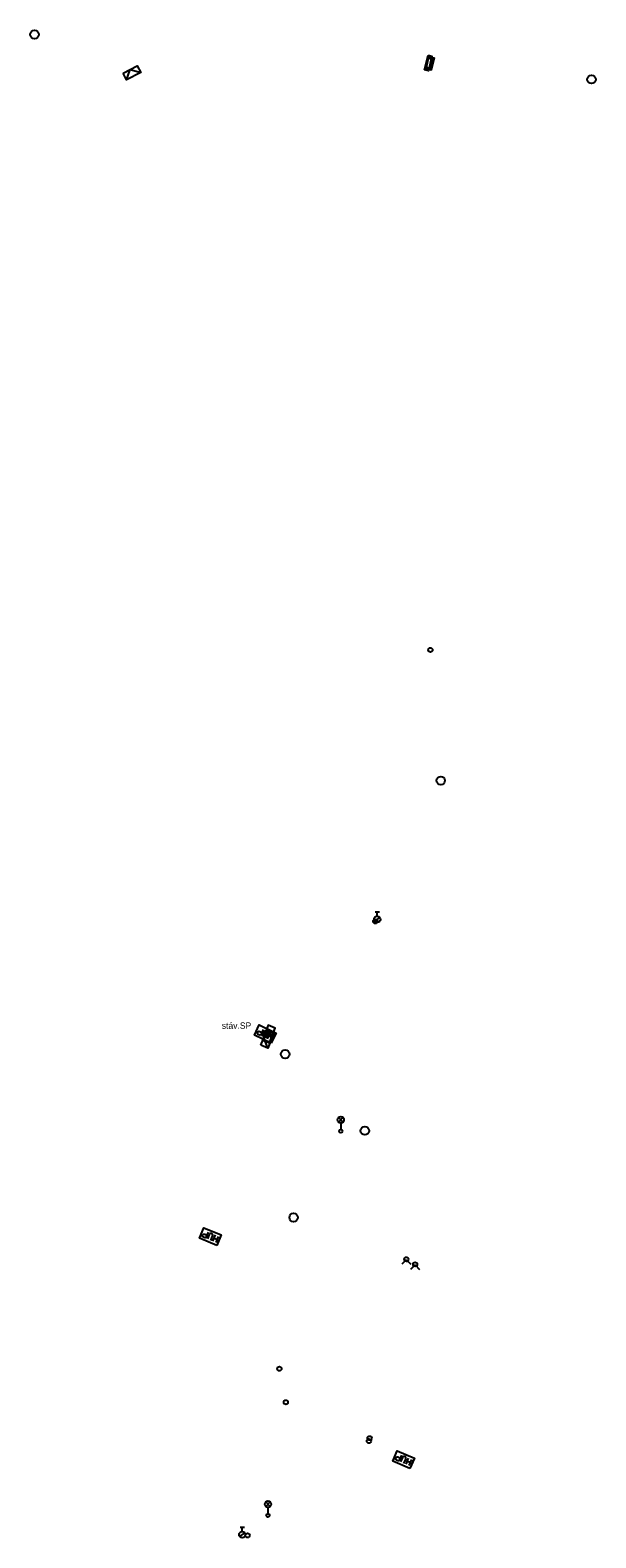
# Model space of a CAD drawing. Extents: x -544660 to -541587, y -1198996 to -1195866.
# Drawn here: x -543850.6 to -543784.4, y -1196848.3 to -1196671.6 of the extents above; entities that cross this region are included whole.
import ezdxf

# ---------------------------------------------------------------- set-up
doc = ezdxf.new("R2010")
doc.units = 0
for name, color, linetype in [('CIZÍ_NADZEM', 7, 'Continuous'), ('ELE_EON', 7, 'Continuous'), ('ELE_EON_POPIS', 7, 'Continuous')]:
    doc.layers.add(name, color=color, linetype=linetype)

msp = doc.modelspace()

# ---------------------------------------------------------------- linework, layer by layer
at = {"layer": 'CIZÍ_NADZEM'}
for p, q in [((-543810.29, -1196776.08), (-543809.7, -1196775.62)), ((-543810.25, -1196774.98), (-543809.75, -1196774.98)), ((-543810, -1196775.48), (-543810, -1196774.98)), ((-543814.53, -1196799.61), (-543814.01, -1196799.08)), ((-543814, -1196799.6), (-543814.53, -1196799.08)), ((-543814.27, -1196799.72), (-543814.27, -1196800.47)), ((-543806.6, -1196815.75), (-543807.13, -1196816.28)), ((-543806.6, -1196815.75), (-543806.07, -1196816.28)), ((-543805.57, -1196816.34), (-543806.1, -1196816.87)), ((-543805.57, -1196816.34), (-543805.04, -1196816.87)), ((-543823.05, -1196844.65), (-543822.53, -1196844.12)), ((-543822.52, -1196844.65), (-543823.05, -1196844.12)), ((-543822.79, -1196844.76), (-543822.79, -1196845.51)), ((-543826.05, -1196847.08), (-543825.55, -1196847.08)), ((-543825.8, -1196847.58), (-543825.8, -1196847.08)), ((-543826.09, -1196848.19), (-543825.5, -1196847.73))]:
    msp.add_line(p, q, dxfattribs=at)
for points in [[(-543822.4, -1196790.38), (-543824.38, -1196789.42), (-543823.81, -1196788.23), (-543821.83, -1196789.19), (-543822.4, -1196790.38)], [(-543823.34, -1196788.77), (-543823.67, -1196789.46)], [(-543823.67, -1196789.46), (-543823.93, -1196789.34), (-543823.99, -1196789.26), (-543824.01, -1196789.22), (-543824.01, -1196789.14), (-543823.96, -1196789.04), (-543823.9, -1196788.99), (-543823.85, -1196788.97), (-543823.75, -1196788.98), (-543823.5, -1196789.1)], [(-543823.08, -1196789.75), (-543822.84, -1196789.25), (-543822.82, -1196789.14), (-543822.85, -1196789.04), (-543822.91, -1196788.97), (-543822.97, -1196788.94), (-543823.07, -1196788.94), (-543823.16, -1196788.97), (-543823.23, -1196789.06), (-543823.47, -1196789.56)], [(-543822.54, -1196789.15), (-543822.88, -1196789.84)], [(-543822.32, -1196789.71), (-543822.72, -1196789.51)], [(-543822.48, -1196790.03), (-543822.15, -1196789.34)], [(-543828.77, -1196814.06), (-543830.8, -1196813.22), (-543830.3, -1196812), (-543828.26, -1196812.84), (-543828.77, -1196814.06)], [(-543830.09, -1196813.22), (-543830.35, -1196813.11), (-543830.42, -1196813.04), (-543830.44, -1196812.99), (-543830.44, -1196812.91), (-543830.4, -1196812.81), (-543830.34, -1196812.76), (-543830.3, -1196812.74), (-543830.2, -1196812.74), (-543829.93, -1196812.85)], [(-543829.79, -1196812.51), (-543830.09, -1196813.22)], [(-543829.48, -1196813.47), (-543829.27, -1196812.96), (-543829.25, -1196812.85), (-543829.29, -1196812.75), (-543829.36, -1196812.68), (-543829.42, -1196812.66), (-543829.52, -1196812.66), (-543829.6, -1196812.7), (-543829.67, -1196812.79), (-543829.89, -1196813.3)], [(-543828.98, -1196812.84), (-543829.28, -1196813.55)], [(-543828.73, -1196813.39), (-543829.14, -1196813.22)], [(-543828.87, -1196813.72), (-543828.57, -1196813.01)], [(-543806.17, -1196840.21), (-543808.19, -1196839.33), (-543807.67, -1196838.12), (-543805.65, -1196839), (-543806.17, -1196840.21)], [(-543807.48, -1196839.34), (-543807.74, -1196839.23), (-543807.81, -1196839.16), (-543807.83, -1196839.11), (-543807.83, -1196839.04), (-543807.78, -1196838.93), (-543807.73, -1196838.88), (-543807.68, -1196838.86), (-543807.58, -1196838.86), (-543807.32, -1196838.98)], [(-543807.17, -1196838.64), (-543807.48, -1196839.34)], [(-543806.87, -1196839.61), (-543806.65, -1196839.1), (-543806.64, -1196838.99), (-543806.67, -1196838.89), (-543806.74, -1196838.82), (-543806.8, -1196838.8), (-543806.9, -1196838.8), (-543806.99, -1196838.84), (-543807.06, -1196838.92), (-543807.28, -1196839.43)], [(-543806.37, -1196838.99), (-543806.67, -1196839.69)], [(-543806.12, -1196839.54), (-543806.53, -1196839.36)], [(-543806.27, -1196839.87), (-543805.96, -1196839.16)]]:
    msp.add_lwpolyline(points, dxfattribs=at)
for centre, radius in [((-543850.13, -1196672.14), 0.5), ((-543784.91, -1196677.41), 0.5), ((-543803.77, -1196744.27), 0.25), ((-543802.57, -1196759.59), 0.5), ((-543810.23, -1196776.1), 0.25), ((-543810, -1196775.85), 0.375), ((-543820.79, -1196791.65), 0.5), ((-543814.27, -1196799.34), 0.375), ((-543814.27, -1196800.67), 0.2), ((-543811.44, -1196800.62), 0.5), ((-543819.79, -1196810.79), 0.5), ((-543806.59, -1196815.69), 0.25), ((-543805.56, -1196816.28), 0.25), ((-543821.45, -1196828.52), 0.25), ((-543820.7, -1196832.44), 0.25), ((-543810.9, -1196836.65), 0.25), ((-543810.97, -1196836.99), 0.25), ((-543822.79, -1196844.39), 0.375), ((-543822.79, -1196845.71), 0.2), ((-543825.8, -1196847.96), 0.375), ((-543825.18, -1196848.05), 0.25)]:
    msp.add_circle(centre, radius, dxfattribs=at)
at = {"layer": 'ELE_EON'}
for points in [[(-543804.05, -1196674.58), (-543803.61, -1196674.68), (-543804.01, -1196676.4), (-543804.45, -1196676.3)], [(-543804.45, -1196676.3), (-543804.05, -1196674.58)], [(-543839.34, -1196677.48), (-543838.93, -1196676.25), (-543837.68, -1196676.6)], [(-543822.79, -1196790.94), (-543823.29, -1196789.74), (-543822.11, -1196789.2)]]:
    msp.add_lwpolyline(points, dxfattribs=at)
for points in [[(-543803.35, -1196674.88), (-543803.69, -1196676.34), (-543804.42, -1196676.17), (-543804.08, -1196674.71)], [(-543803.54, -1196675.04), (-543803.79, -1196676.11), (-543804.23, -1196676.01), (-543803.98, -1196674.94)], [(-543839.76, -1196676.69), (-543838.1, -1196675.81), (-543837.68, -1196676.6), (-543839.34, -1196677.48)], [(-543822.61, -1196790.34), (-543821.93, -1196788.6), (-543822.76, -1196788.27), (-543823.45, -1196790.01)], [(-543823.63, -1196790.61), (-543822.94, -1196788.87), (-543822.11, -1196789.2), (-543822.79, -1196790.94)], [(-543822.84, -1196789.75), (-543822.5, -1196788.88), (-543822.53, -1196788.86), (-543822.88, -1196789.73)]]:
    msp.add_lwpolyline(points, close=True, dxfattribs=at)

# ---------------------------------------------------------------- texts
at = {"layer": 'ELE_EON_POPIS'}
msp.add_text('stáv.SP', height=0.75, dxfattribs=at).set_placement((-543828.2, -1196788.68))

doc.saveas('drawing.dxf')
